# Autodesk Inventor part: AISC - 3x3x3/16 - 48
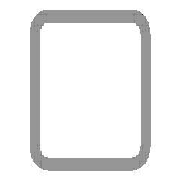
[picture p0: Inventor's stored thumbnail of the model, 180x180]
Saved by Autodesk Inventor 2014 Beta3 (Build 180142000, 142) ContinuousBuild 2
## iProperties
_CCFamilyMember: 9
_CCFamilyDisplayName: ANSI AISC (Square) - Tube
_FrameMemberDoc: Frame Member File
_Version: 15.0.0
_GetPNFromCC: 1
Created: 2011-01
Part Number: AISC - 3x3x3/16 - 48
Material: Steel, Mild
Description: Tube
Document SubType Name: Modeling
Standard: ANSI
Designer: Beta-8540w
Standards Organization: ANSI
Language: en-US
Size Designation: 3x3x3/16
Categories: <MemberInstance><Categories><Category DisplayName="Structural Shapes" InternalName="089c4875-fa83-4c05-b084-43b9cc11f5ed" Mnemonic="GRDR"><CategoryParameter Dis
Stock Number: 3x3x3/16
Density: 7.86 g/cm^3
Appearance: Steel
IsCustomPart: 1
G_L: 48.000 in
G_W: 3.000 in
G_H: 3.000 in
Author: Beta-8540w
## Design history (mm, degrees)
node "Start plane"
node "End plane"
sketch "Sketch"
  geometry: L1 (-38.1, -28.575)-(-38.1, 28.575); L2 (-28.575, 38.1)-(28.575, 38.1); L3 (38.1, 28.575)-(38.1, -28.575); L4 (28.575, -38.1)-(-28.575, -38.1); L5 (-28.575, 33.337)-(28.575, 33.338); L6 (33.338, 28.575)-(33.338, -28.575); L7 (28.575, -33.337)-(-28.575, -33.338); L8 (-33.338, -28.575)-(-33.338, 28.575); L9 (0, 56.102)-(0, -56.102) reference; L10 (-56.102, 0)-(56.102, 0) reference; A1 r 9.525 centre (-28.575, -28.575) between (-38.1, -28.575) and (-28.575, -38.1); A2 r 9.525 centre (-28.575, 28.575) between (-28.575, 38.1) and (-38.1, 28.575); A3 r 9.525 centre (28.575, 28.575) between (38.1, 28.575) and (28.575, 38.1); A4 r 9.525 centre (28.575, -28.575) between (28.575, -38.1) and (38.1, -28.575); A5 r 4.763 centre (-28.575, 28.575) between (-28.575, 33.337) and (-33.338, 28.575); A6 r 4.763 centre (28.575, 28.575) between (33.338, 28.575) and (28.575, 33.338); A7 r 4.763 centre (28.575, -28.575) between (28.575, -33.337) and (33.338, -28.575); A8 r 4.763 centre (-28.575, -28.575) between (-33.338, -28.575) and (-28.575, -33.338)
  constraints: 16 end point, 16 point on circle, 8 centre point, 8 tangent, 4 parallel, 3 equal radius, 2 perpendicular, 7 other
  dimensions: "d10" = 76.2 distance between parallel lines of L2 L4 (= G_H); "d11" = 76.2 distance between parallel lines of L1 L3 (= G_W); "d12" = 4.7625 distance between parallel lines of L3 L6 (= G_T); "d15" = 38.1 distance between parallel lines of L2 L10 (= 0.5 x d10); "d16" = 38.1 distance between parallel lines of L9 L3 (= 0.5 x d11); "d17" = 9.525 radius of A1 (= G_IR)
extrude "Body" new body sketch "Sketch" stored distance "d3" = 1219.2 (= G_L); taper "d4" = 0 deg
node "Driven Length"
  sketch "Sketch3"
    geometry: L1 (0, 0)-(10, 0) reference
    constraints: 2 end point, 1 horizontal
  workplane "Work Plane3"
  sketch "Sketch4"
    geometry: L1 (-2, 0)-(12, 0) reference; L2 (-2, 1219.2)-(12, 1219.2) reference
    dimensions: "d19" = 1219.2 distance between parallel lines of L1 L2 (derived)
body "Solid1"
other parameters: "G_W" = 76.2 [user parameter; used in 1 equation term], "G_H" = 76.2 [user parameter; used in 1 equation term], "G_T" = 4.7625 [user parameter; used in 1 equation term], "G_IR" = 9.525 [user parameter; used in 1 equation term], "G_L" = 1219.2 (= d19) [user parameter; used in 1 equation term], "G_OFFSET_START" = 0 [user parameter; used in 1 equation term], "G_OFFSET_END" = 0 [user parameter; used in 1 equation term], "d13" = 0 (computed from G_OFFSET_START), "d14" = 1219.2 (= G_OFFSET_END + B_L), "B_L" = 1219.2 [user parameter; used in 1 equation term], "d18" = 90 deg
